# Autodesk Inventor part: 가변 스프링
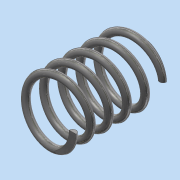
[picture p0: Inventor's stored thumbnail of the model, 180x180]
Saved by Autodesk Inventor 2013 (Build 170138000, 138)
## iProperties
Created: 2018-10
Part Number: 가변 스프링
Material: 스테인리스강
Document SubType Name: Modeling
Designer: Administrator
Density: 8.08 g/cm^3
Mass: 6.26905 g
Surface Area: 15.7665 cm^2
Volume: 0.775873 cm^3
Author: Administrator
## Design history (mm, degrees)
sketch "스케치1"
  geometry: L1 (0, 0)-(0, 30.493); L2 (0.539, 0)-(8, 0); L3 (0, 30.493)-(8, 30.493); C1 r 1 at (8, 0)
  constraints: 6 end point, 1 centre point, 1 horizontal alignment, 1 parallel, 1 perpendicular, 1 vertical
  dimensions: "d0" = 30.49301 distance of L1.start L1.end (derived); "d1" = 2 diameter of C1; "d2" = 16 diameter of L2.end L1; "d3" = 8 distance of L1.end L3.end
feature "코일1" sketch "스케치1" pitch "d4" = 10; turns "d6" = 5; dims "d5" = 30.49301 (= d0), "d7" = 0, angle "d8" = 90 deg, angle "d9" = 90 deg, "d10" = 0, "d11" = 0
sketch "스케치2"
  geometry: L1 (30.493, 11)-(0, 11); L2 (0, 11)-(0, -11); L3 (0, -11)-(30.493, -11); L4 (30.493, -11)-(30.493, 11); 2 further points
  constraints: 8 end point, 2 parallel, 1 coincident, 1 horizontal, 1 midpoint, 1 perpendicular
  dimensions: "d12" = 30.49301 distance of L3.end L2.end (derived); "d13" = 22 distance of L2.end L1.end
extrude "돌출1" sketch "스케치2" stored distance "d14" = 0; taper "d15" = 0 deg
node "솔리드1"
